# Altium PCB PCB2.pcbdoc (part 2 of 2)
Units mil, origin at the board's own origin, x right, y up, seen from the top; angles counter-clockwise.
Board outline 6543.11 x 5085 mil, 2 copper layers (Top Layer, Bottom Layer); 225 components, 109 nets, 561 pads, 168 vias.
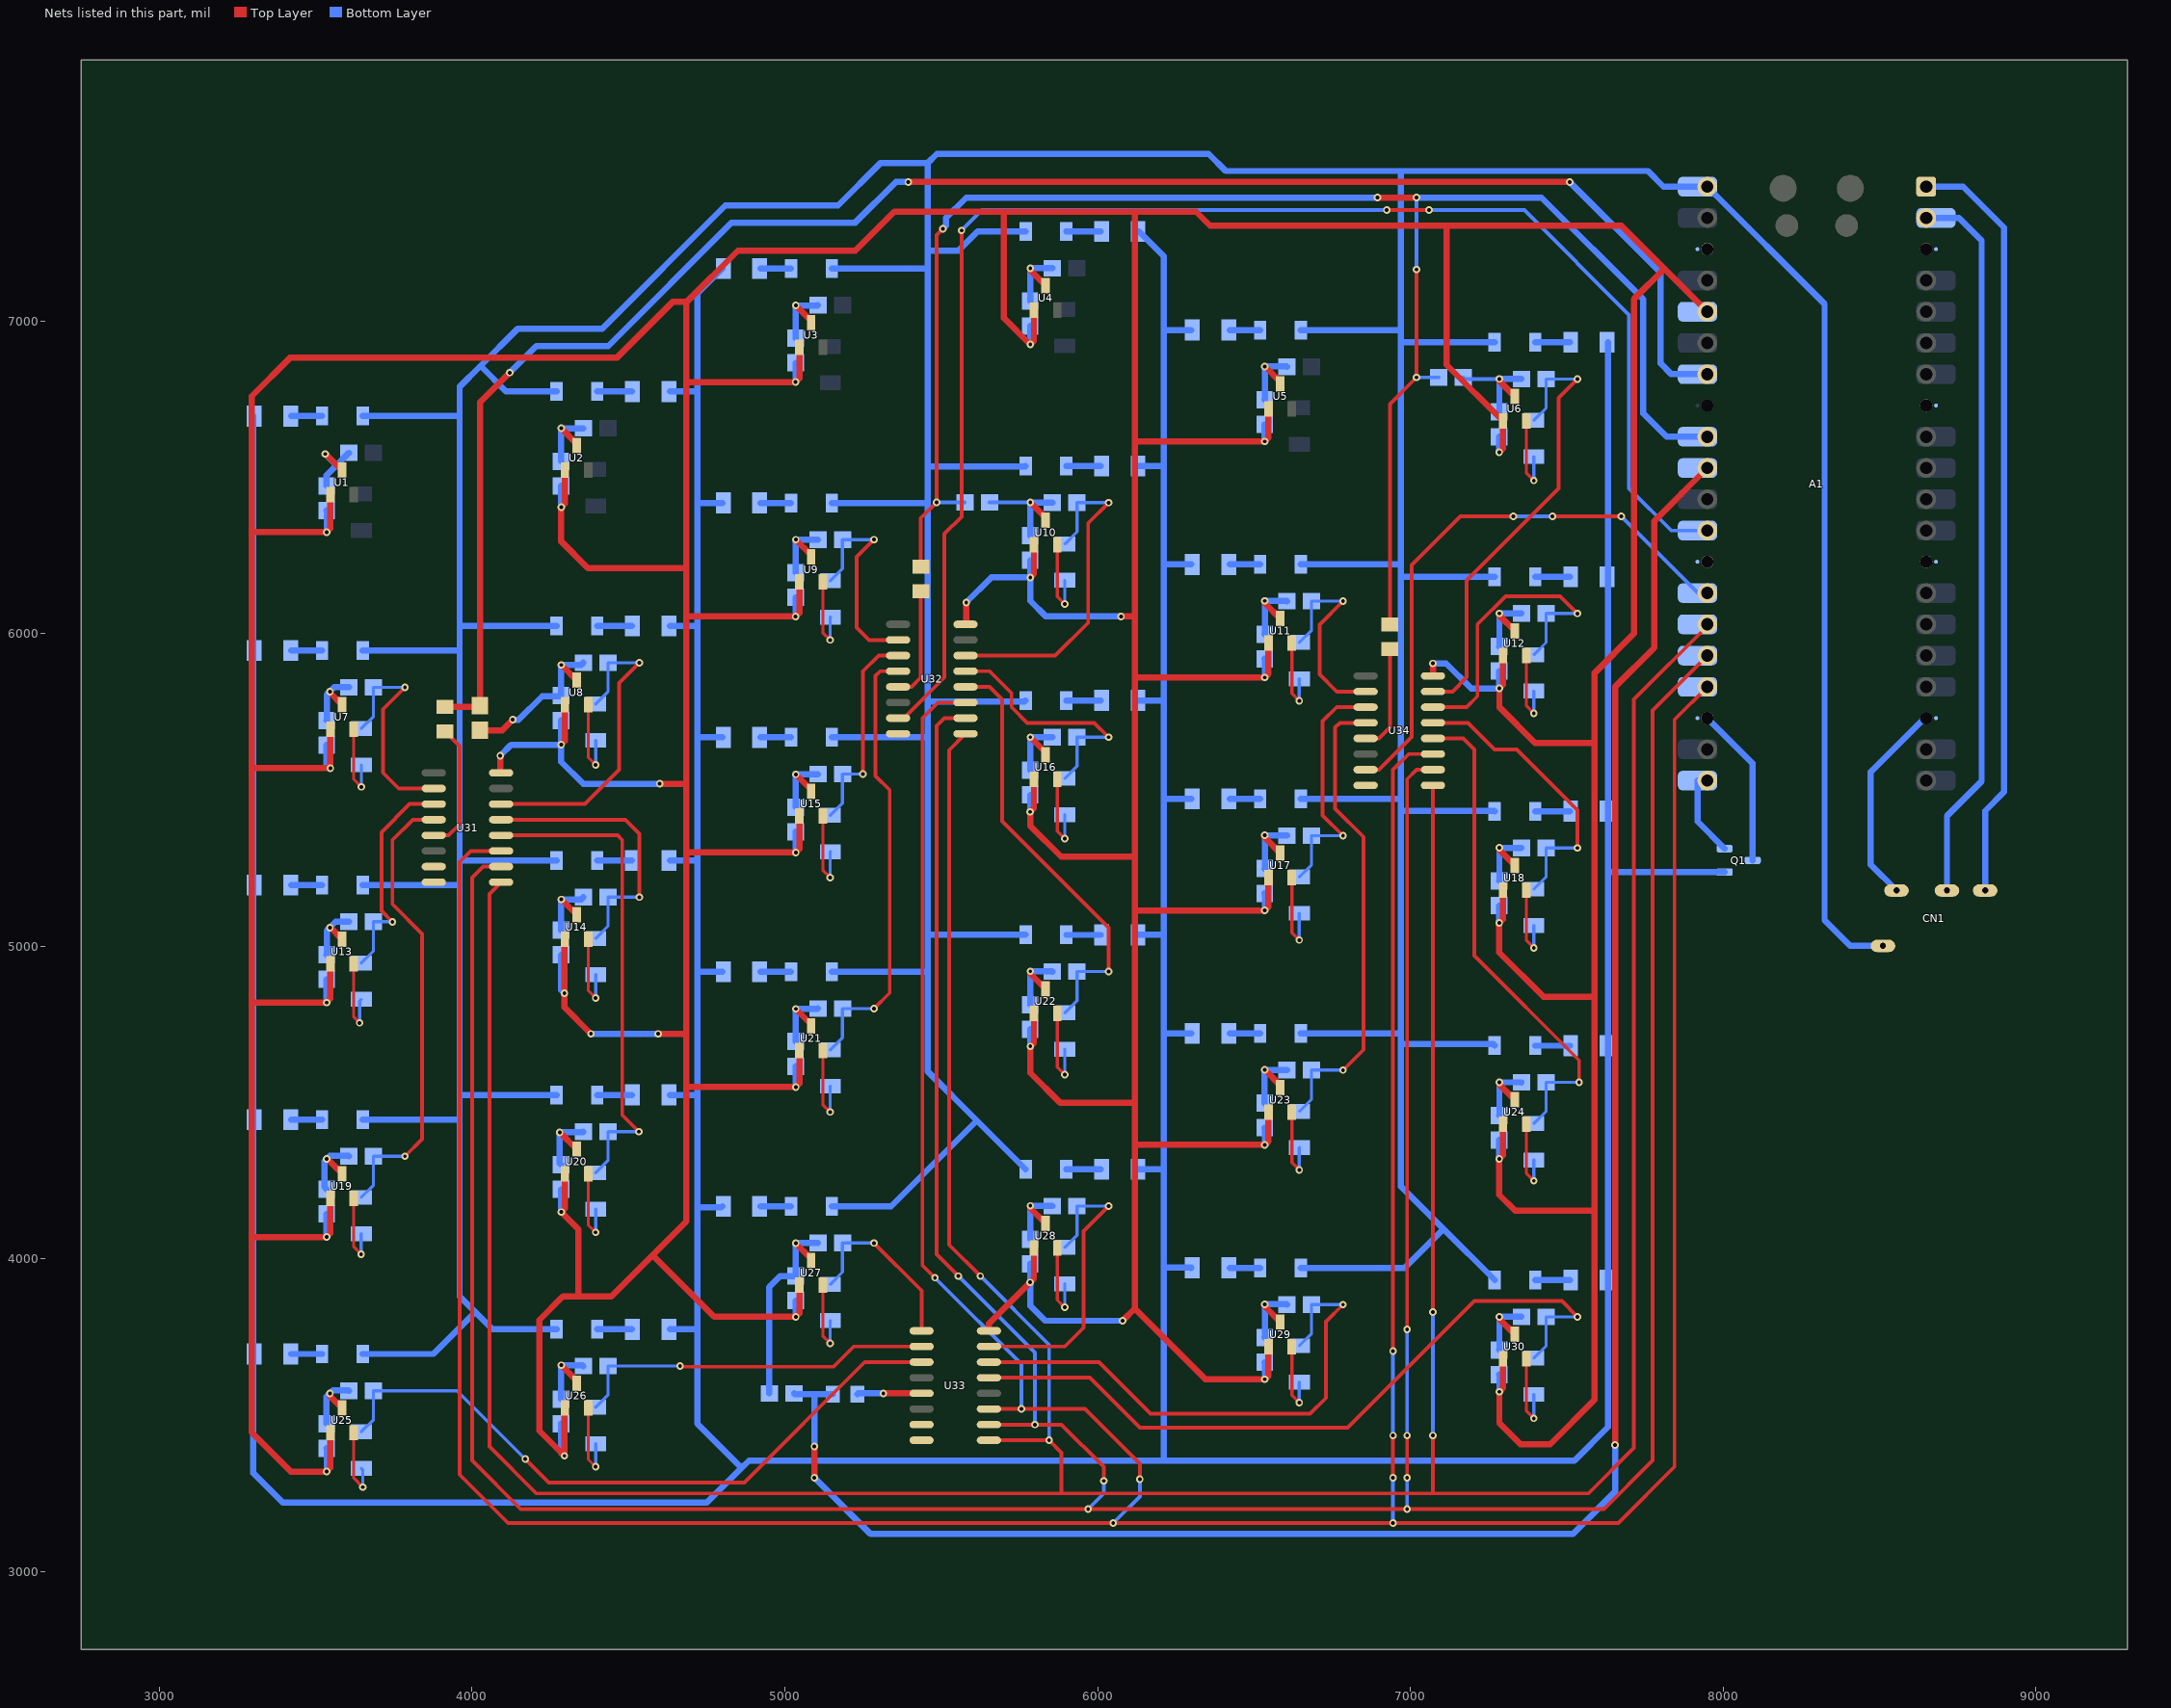
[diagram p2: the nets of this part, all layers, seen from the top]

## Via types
v1: diameter 24.02, hole 12.01, Top Layer to Bottom Layer, 168 vias

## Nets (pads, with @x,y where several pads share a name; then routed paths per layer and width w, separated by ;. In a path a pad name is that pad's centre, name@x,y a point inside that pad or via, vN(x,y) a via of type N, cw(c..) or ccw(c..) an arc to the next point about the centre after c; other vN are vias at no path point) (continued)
$1N19276: R36.2 U6.2 | length 276.8
  Top Layer w10: U6.2@7371.42,6680.31 7371.42,6513.58 v1(7395,6490)
  Bottom Layer w10: v1(7395,6490) 7395,6565.91 R36.2@7395.55,6566.47
$1N19282: C12.2 R36.1 U34.15 | length 1476.1
  Top Layer w12: U34.15@7072.7,5815 7135,5815 7180.45,5860.45 7180.45,6170.45 7475,6465 7475,6754.69 v1(7535,6814.69)
  Bottom Layer w10: R36.1@7395.55,6682.9 7434.41,6721.76 C12.2@7434.41,6814.69 v1(7535,6814.69)
$1N20121: C22.2 R41.1 U34.2 | length 683.7
  Top Layer w12: v1(6785,6104.06) 6710,6029.06 6710,5870 6765,5815 U34.2@6857.3,5815
  Bottom Layer w10: R41.1@6645.55,5972.28 6684.41,6011.13 C22.2@6684.41,6104.06 v1(6785,6104.06)
$1N20126: R41.2 U11.2 | length 265.5
  Top Layer w10: U11.2@6621.42,5969.69 6621.42,5808.58 v1(6645,5785)
  Bottom Layer w10: v1(6645,5785) 6645,5855.28 R41.2@6645.55,5855.84
$1N20136: R42.2 U12.2 | length 266.8
  Top Layer w10: U12.2@7371.42,5930.31 7371.42,5768.58 v1(7395,5745)
  Bottom Layer w10: v1(7395,5745) 7395,5815.91 R42.2@7395.55,5816.47
$1N20142: C20.2 R40.1 U32.14 | length 1095.2
  Top Layer w12: U32.14@5577.7,5930 5865,5930 5970,6035 5970,6354.02 v1(6035,6419.02)
  Bottom Layer w10: R40.1@5895.55,6287.24 5934.41,6326.09 C20.2@5934.41,6419.02 v1(6035,6419.02)
$1N20147: R40.2 U10.2 | length 275.4
  Top Layer w10: U10.2@5871.42,6284.65 5871.42,6118.58 v1(5895,6095)
  Bottom Layer w10: v1(5895,6095) 5895,6170.24 R40.2@5895.55,6170.8
$1N20149: R38.2 U8.2 | length 281.8
  Top Layer w10: U8.2@4371.42,5772.83 4371.42,5603.58 v1(4395,5580)
  Bottom Layer w10: v1(4395,5580) 4395,5658.43 R38.2@4395.55,5658.98
$1N20151: R39.2 U9.2 | length 269.2
  Top Layer w10: U9.2@5121.42,6166.54 5121.42,6003.58 v1(5145,5980)
  Bottom Layer w10: v1(5145,5980) 5145,6052.13 R39.2@5145.55,6052.69
$1N20153: C18.2 R39.1 U32.2 | length 701
  Top Layer w12: v1(5285,6300.91) 5230,6245.91 5230,6020 5270,5980 U32.2@5362.3,5980
  Bottom Layer w10: R39.1@5145.55,6169.13 5184.41,6207.98 C18.2@5184.41,6300.91 v1(5285,6300.91)
$1N20174: C14.2 R37.1 U31.2 | length 733.9
  Top Layer w12: v1(3785,5828.46) 3715,5758.46 3715,5555 3765,5505 U31.2@3877.3,5505
  Bottom Layer w10: R37.1@3645.55,5696.68 3684.41,5735.54 C14.2@3684.41,5828.46 v1(3785,5828.46)
$1N20179: R37.2 U7.2 | length 264.3
  Top Layer w10: U7.2@3621.42,5694.09 3621.42,5534.14 v1(3645.55,5510)
  Bottom Layer w10: v1(3645.55,5510) R37.2@3645.55,5580.24
$1N20185: C16.2 R38.1 U31.14 | length 1040.5
  Top Layer w12: U31.14@4092.7,5455 4360,5455 4470,5565 4470,5842.2 v1(4535,5907.2)
  Bottom Layer w10: R38.1@4395.55,5775.42 4434.41,5814.28 C16.2@4434.41,5907.2 v1(4535,5907.2)
$1N20206: C24.2 R42.1 U34.14 | length 1015.5
  Top Layer w12: U34.14@7072.7,5765 7180,5765 7215,5800 7215,6030 7305,6120 7479.69,6120 v1(7535,6064.69)
  Bottom Layer w10: R42.1@7395.55,5932.9 7434.41,5971.76 C24.2@7434.41,6064.69 v1(7535,6064.69)
$1N21045: C34.2 R47.1 U34.3 | length 797.3
  Top Layer w12: v1(6785,5354.06) 6720,5419.06 6720,5720 6765,5765 U34.3@6857.3,5765
  Bottom Layer w10: R47.1@6645.55,5222.28 6684.41,5261.13 C34.2@6684.41,5354.06 v1(6785,5354.06)
$1N21050: R47.2 U17.2 | length 295.5
  Top Layer w10: U17.2@6621.42,5219.69 6621.42,5043.58 v1(6645,5020)
  Bottom Layer w10: v1(6645,5020) 6645,5105.28 R47.2@6645.55,5105.84
$1N21060: R48.2 U18.2 | length 266.8
  Top Layer w10: U18.2@7371.42,5180.31 7371.42,5018.58 v1(7395,4995)
  Bottom Layer w10: v1(7395,4995) 7395,5065.91 R48.2@7395.55,5066.47
$1N21066: C32.2 R46.1 U32.13 | length 819.5
  Top Layer w12: U32.13@5577.7,5880 5655,5880 5725,5810 5725,5765 5775,5715 5989.02,5715 v1(6035,5669.02)
  Bottom Layer w10: R46.1@5895.55,5537.24 5934.41,5576.09 C32.2@5934.41,5669.02 v1(6035,5669.02)
$1N21071: R46.2 U16.2 | length 275.4
  Top Layer w10: U16.2@5871.42,5534.65 5871.42,5368.58 v1(5895,5345)
  Bottom Layer w10: v1(5895,5345) 5895,5420.24 R46.2@5895.55,5420.8
$1N21073: R44.2 U14.2 | length 271.8
  Top Layer w10: U14.2@4371.42,5022.83 4371.42,4858.58 v1(4395,4835)
  Bottom Layer w10: v1(4395,4835) 4395,4908.43 R44.2@4395.55,4908.98
$1N21075: R45.2 U15.2 | length 289.2
  Top Layer w10: U15.2@5121.42,5416.54 5121.42,5243.58 v1(5145,5220)
  Bottom Layer w10: v1(5145,5220) 5145,5302.13 R45.2@5145.55,5302.69
$1N21077: C30.2 R45.1 U32.3 | length 675.6
  Top Layer w12: v1(5250,5550.91) 5250,5880 5300,5930 U32.3@5362.3,5930
  Bottom Layer w10: R45.1@5145.55,5419.13 5184.41,5457.98 C30.2@5184.41,5550.91 v1(5250,5550.91)
$1N21098: C26.2 R43.1 U31.3 | length 714.1
  Top Layer w12: v1(3745,5078.46) 3710,5113.46 3710,5365 3800,5455 U31.3@3877.3,5455
  Bottom Layer w10: R43.1@3645.55,4946.68 3684.41,4985.54 C26.2@3684.41,5078.46 v1(3745,5078.46)
$1N21103: R43.2 U13.2 | length 274.3
  Top Layer w10: U13.2@3621.42,4944.09 3621.42,4773.58 v1(3640,4755)
  Bottom Layer w10: v1(3640,4755) 3640,4824.69 R43.2@3645.55,4830.24
$1N21109: C28.2 R44.1 U31.13 | length 912.2
  Top Layer w12: U31.13@4092.7,5405 4490,5405 4535,5360 v1(4535,5157.2)
  Bottom Layer w10: R44.1@4395.55,5025.42 4434.41,5064.28 C28.2@4434.41,5157.2 v1(4535,5157.2)
$1N21130: C36.2 R48.1 U34.13 | length 947.1
  Top Layer w12: U34.13@7072.7,5715 7185,5715 7270,5630 7340,5630 7535,5435 v1(7535,5314.69)
  Bottom Layer w10: R48.1@7395.55,5182.9 7434.41,5221.76 C36.2@7434.41,5314.69 v1(7535,5314.69)
$1N21969: C46.2 R53.1 U34.4 | length 1512.1
  Top Layer w12: v1(6785,4604.06) 6850,4669.06 6850,5350 6760,5440 6760,5700 6775,5715 U34.4@6857.3,5715
  Bottom Layer w10: R53.1@6645.55,4472.28 6684.41,4511.13 C46.2@6684.41,4604.06 v1(6785,4604.06)
$1N21974: R53.2 U23.2 | length 265.5
  Top Layer w10: U23.2@6621.42,4469.69 6621.42,4308.58 v1(6645,4285)
  Bottom Layer w10: v1(6645,4285) 6645,4355.28 R53.2@6645.55,4355.84
$1N21984: R54.2 U24.2 | length 256.8
  Top Layer w10: U24.2@7371.42,4430.31 7371.42,4273.58 v1(7395,4250)
  Bottom Layer w10: v1(7395,4250) 7395,4315.91 R54.2@7395.55,4316.47
$1N21990: C44.2 R52.1 U32.12 | length 1394.2
  Top Layer w12: U32.12@5577.7,5830 5655,5830 5695,5790 5695,5400 6035,5060 v1(6035,4919.02)
  Bottom Layer w10: R52.1@5895.55,4787.24 5934.41,4826.09 C44.2@5934.41,4919.02 v1(6035,4919.02)
$1N21995: R52.2 U22.2 | length 285.4
  Top Layer w10: U22.2@5871.42,4784.65 5871.42,4613.58 v1(5895,4590)
  Bottom Layer w10: v1(5895,4590) 5895,4670.24 R52.2@5895.55,4670.8
$1N21997: R50.2 U20.2 | length 271.8
  Top Layer w10: U20.2@4371.42,4272.83 4371.42,4108.58 v1(4395,4085)
  Bottom Layer w10: v1(4395,4085) 4395,4158.43 R50.2@4395.55,4158.98
$1N21999: R51.2 U21.2 | length 289.2
  Top Layer w10: U21.2@5121.42,4666.54 5121.42,4493.58 v1(5145,4470)
  Bottom Layer w10: v1(5145,4470) 5145,4552.13 R51.2@5145.55,4552.69
$1N22001: C42.2 R51.1 U32.4 | length 1430.4
  Top Layer w12: v1(5285,4800.91) 5335,4850.91 5335,5500 5290,5545 5290,5865 5305,5880 U32.4@5362.3,5880
  Bottom Layer w10: R51.1@5145.55,4669.13 5184.41,4707.98 C42.2@5184.41,4800.91 v1(5285,4800.91)
$1N22022: C38.2 R49.1 U31.4 | length 1481.4
  Top Layer w12: v1(3785,4328.46) 3840,4383.46 3840,5040 3745,5135 3745,5340 3810,5405 U31.4@3877.3,5405
  Bottom Layer w10: R49.1@3645.55,4196.68 3684.41,4235.54 C38.2@3684.41,4328.46 v1(3785,4328.46)
$1N22027: R49.2 U19.2 | length 254.3
  Top Layer w10: U19.2@3621.42,4194.09 3621.42,4038.58 v1(3645,4015)
  Bottom Layer w10: v1(3645,4015) 3645,4079.69 R49.2@3645.55,4080.24
$1N22033: C40.2 R50.1 U31.12 | length 1594.4
  Top Layer w12: U31.12@4092.7,5355 4465,5355 4480,5340 4480,4460 v1(4532.8,4407.2)
  Bottom Layer w10: R50.1@4395.55,4275.42 4434.41,4314.28 C40.2@4434.41,4407.2 v1(4532.8,4407.2)
$1N22054: C48.2 R54.1 U34.12 | length 1604.3
  Top Layer w12: U34.12@7072.7,5665 7170,5665 7205,5630 7205,4970 7540,4635 v1(7540,4564.69)
  Bottom Layer w10: R54.1@7395.55,4432.9 7434.41,4471.76 C48.2@7434.41,4564.69 v1(7540,4564.69)
$1N22893: C58.2 R59.1 U33.14 | length 1736.7
  Top Layer w12: U33.14@5652.7,3670 6005,3670 6170,3505 6680,3505 6730,3555 6730,3799.06 v1(6785,3854.06)
  Bottom Layer w10: R59.1@6645.55,3722.28 6684.41,3761.13 C58.2@6684.41,3854.06 v1(6785,3854.06)
$1N22898: R59.2 U29.2 | length 255.5
  Top Layer w10: U29.2@6621.42,3719.69 6621.42,3563.58 v1(6645,3540)
  Bottom Layer w10: v1(6645,3540) 6645,3605.28 R59.2@6645.55,3605.84
$1N22908: R60.2 U30.2 | length 276.8
  Top Layer w10: U30.2@7371.42,3680.32 7371.42,3513.58 v1(7395,3490)
  Bottom Layer w10: v1(7395,3490) 7395,3565.91 R60.2@7395.55,3566.47
$1N22914: C56.2 R58.1 U33.15 | length 997.8
  Top Layer w12: U33.15@5652.7,3720 5895,3720 5955,3780 5955,4089.02 v1(6035,4169.02)
  Bottom Layer w10: R58.1@5895.55,4037.24 5934.41,4076.09 C56.2@5934.41,4169.02 v1(6035,4169.02)
$1N22919: R58.2 U28.2 | length 275.4
  Top Layer w10: U28.2@5871.42,4034.65 5871.42,3868.58 v1(5895,3845)
  Bottom Layer w10: v1(5895,3845) 5895.55,3845.55 R58.2@5895.55,3920.8
$1N22921: R56.2 U26.2 | length 271.8
  Top Layer w10: U26.2@4371.42,3522.83 4371.42,3358.58 v1(4395,3335)
  Bottom Layer w10: v1(4395,3335) 4395,3408.43 R56.2@4395.55,3408.98
$1N22923: R57.2 U27.2 | length 269.2
  Top Layer w10: U27.2@5121.42,3916.54 5121.42,3753.58 v1(5145,3730)
  Bottom Layer w10: v1(5145,3730) 5145,3802.13 R57.2@5145.55,3802.69
$1N22925: C54.2 R57.1 U33.1 | length 592.5
  Top Layer w12: v1(5285,4050.91) 5437.3,3898.61 U33.1@5437.3,3770
  Bottom Layer w10: R57.1@5145.55,3919.13 5184.41,3957.98 C54.2@5184.41,4050.91 v1(5285,4050.91)
$1N22946: C50.2 R55.1 U33.3 | length 2181.9
  Top Layer w12: v1(4170,3360) 4170,3359.82 4244.82,3285 4870,3285 5255,3670 U33.3@5437.3,3670
  Bottom Layer w10: R55.1@3645.55,3446.68 3684.41,3485.54 C50.2@3684.41,3578.46 3951.54,3578.46 v1(4170,3360)
$1N22951: R55.2 U25.2 | length 248
  Top Layer w10: U25.2@3621.42,3444.09 3621.42,3298.58 v1(3650,3270)
  Bottom Layer w10: R55.2@3645.55,3330.24 3650,3325.8 v1(3650,3270)
$1N22957: C52.2 R56.1 U33.2 | length 1178.6
  Top Layer w12: v1(4665,3657.2) 4667.2,3655 5155,3655 5220,3720 U33.2@5437.3,3720
  Bottom Layer w10: R56.1@4395.55,3525.42 4434.41,3564.28 C52.2@4434.41,3657.2 v1(4665,3657.2)
$1N22978: C60.2 R60.1 U33.13 | length 2385.6
  Top Layer w12: U33.13@5652.7,3620 5975,3620 6135,3460 6800,3460 7205,3865 7484.69,3865 v1(7535,3814.68)
  Bottom Layer w10: R60.1@7395.55,3682.91 7434.41,3721.76 C60.2@7434.41,3814.68 v1(7535,3814.68)
$1N29883: R63.2 U34.5 | length 342.8
  Top Layer w12: U34.5@6857.3,5665 6900,5665 6935,5700 R63.2@6935,5950.63
$1N29959: R64.2 U33.5 | length 206.8
  Top Layer w20: v1(5315,3570) U33.5@5437.3,3570
  Bottom Layer w20: R64.2@5231.66,3567.21 5234.45,3570 v1(5315,3570)
$1N30613: R61.2 U31.5 | length 414.6
  Top Layer w12: U31.5@3877.3,5355 3925,5355 3960,5390 3960,5640.63 R61.2@3912.77,5687.86
$1N30615: R62.2 U32.5 | length 360.8
  Top Layer w12: U32.5@5362.3,5830 5405,5830 5435,5860 R62.2@5435,6135.63
$2N2161: Q1.1 R1.1 R2.1 R3.1 R4.1 R5.1 R6.1 R7.1 R8.1 R9.1 R10.1 R11.1 R12.1 R13.1 R14.1 R15.1 R16.1 R17.1 R18.1 R19.1 R20.1 R21.1 R22.1 R23.1 R24.1 R25.1 R26.1 R27.1 R28.1 R29.1 R30.1 | length 21120.1
  Bottom Layer w19.68: R30.1@7632.24,3932.2 7632.24,5237.19 R6.1@7632.24,6932.2
  Bottom Layer w20: R1.1@3300.2,6695.98 3300.2,3314.8 3395,3220 4750,3220 4861.37,3331.37 ; R26.1@4632.24,3774.72 4718.49,3774.72 4720,3773.21 ; R20.1@4632.24,4524.72 4717.79,4524.72 4720,4526.93 ; R14.1@4632.24,5274.72 4719.97,5274.72 ; R8.1@4632.24,6024.72 4719.78,6024.72 4720,6024.94 ; R2.1@4632.24,6774.72 4719.22,6774.72 4720,6773.94 ; R27.1@4800.2,4168.43 4796.59,4164.82 4720,4164.82 ; R21.1@4800.2,4918.43 4722.47,4918.43 4720,4920.9 ; R15.1@4800.2,5668.43 4720.3,5668.43 4720,5668.72 ; R9.1@4800.2,6418.43 4720.48,6418.43 4720,6418.9 ; R3.1@4800.2,7168.43 4720,7088.23 4720,6773.94 ; R28.1@6132.24,4286.54 6210.55,4286.54 6212.42,4288.41 ; R22.1@6132.24,5036.54 6211.42,5036.54 6212.42,5037.54 ; R16.1@6132.24,5786.54 6212.28,5786.54 6212.42,5786.67 ; R10.1@6132.24,6536.54 6211.84,6536.54 6212.42,6537.12 ; R4.1@6132.24,7286.54 6212.42,7206.36 6212.42,6968.83 ; R29.1@6300.2,3971.57 6299.23,3972.54 6212.42,3972.54 ; R23.1@6300.2,4721.57 6216.99,4721.57 6212.42,4726.14 ; R17.1@6300.2,5471.57 6213.5,5471.57 6212.42,5472.66 ; R11.1@6300.2,6221.57 6213.16,6221.57 6212.42,6222.31 ; R5.1@6300.2,6971.57 6215.17,6971.57 6212.42,6968.83 ; R30.1@7632.24,3932.2 7632.24,3462.24 7525,3355 6214.77,3355 ; 7632.24,5237.19 7632.65,5237.6 Q1.1@8005.22,5237.6 ; 4720,3773.21 4720,3472.74 4861.37,3331.37 ; 4720,3773.21 4720,4164.82 ; 4720,4164.82 4720,4526.93 ; 4720,4526.93 4720,4920.9 ; 4720,4920.9 4720,5274.76 4720,5668.72 ; 4720,5668.72 4720,6024.94 ; 4720,6024.94 4720,6418.9 ; 4720,6418.9 4720,6773.94 ; 4861.37,3331.37 4885,3355 6214.77,3355 ; 6212.42,3972.54 6212.42,4288.41 ; 6212.42,3972.54 6212.42,3357.35 6214.77,3355 ; 6212.42,4288.41 6212.42,4726.14 ; 6212.42,4726.14 6212.42,5037.54 ; 6212.42,5037.54 6212.42,5472.66 ; 6212.42,5472.66 6212.42,5786.67 ; 6212.42,5786.67 6212.42,6222.31 ; 6212.42,6222.31 6212.42,6537.12 ; 6212.42,6537.12 6212.42,6968.83
$2N2235: D4.1 R4.2 | length 110.2
  Bottom Layer w19.68: D4.1@5900,7286.54 R4.2@6010.2,7286.54
$2N2237: D1.1 R1.2 | length 97.8
  Bottom Layer w20: R1.2@3422.24,6695.98 D1.1@3520,6695.98
$2N2239: D17.1 R17.2 | length 97.8
  Bottom Layer w20: R17.2@6422.24,5471.57 D17.1@6520,5471.57
$2N2241: D24.1 R24.2 | length 110.2
  Bottom Layer w19.68: D24.1@7400,4682.2 R24.2@7510.2,4682.2
$2N2243: D9.1 R9.2 | length 97.8
  Bottom Layer w20: R9.2@4922.24,6418.43 D9.1@5020,6418.43
$2N2245: D7.1 R7.2 | length 97.8
  Bottom Layer w20: R7.2@3422.24,5945.98 D7.1@3520,5945.98
$2N2247: D21.1 R21.2 | length 97.8
  Bottom Layer w20: R21.2@4922.24,4918.43 D21.1@5020,4918.43
$2N2249: D8.1 R8.2 | length 110.2
  Bottom Layer w20: D8.1@4400,6024.72 R8.2@4510.2,6024.72
$2N2251: D15.1 R15.2 | length 97.8
  Bottom Layer w20: R15.2@4922.24,5668.43 D15.1@5020,5668.43
$2N2253: D12.1 R12.2 | length 110.2
  Bottom Layer w19.68: D12.1@7400,6182.2 R12.2@7510.2,6182.2
$2N2255: D18.1 R18.2 | length 110.2
  Bottom Layer w19.68: D18.1@7400,5432.2 R18.2@7510.2,5432.2
$2N2257: D19.1 R19.2 | length 97.8
  Bottom Layer w20: R19.2@3422.24,4445.98 D19.1@3520,4445.98
$2N2259: D3.1 R3.2 | length 97.8
  Bottom Layer w20: R3.2@4922.24,7168.43 D3.1@5020,7168.43
$2N2261: D13.1 R13.2 | length 97.8
  Bottom Layer w20: R13.2@3422.24,5195.98 D13.1@3520,5195.98
$2N2263: D25.1 R25.2 | length 97.8
  Bottom Layer w20: R25.2@3422.24,3695.98 D25.1@3520,3695.98
$2N2265: D22.1 R22.2 | length 110.2
  Bottom Layer w19.68: D22.1@5900,5036.54 R22.2@6010.2,5036.54
$2N2267: D5.1 R5.2 | length 97.8
  Bottom Layer w20: R5.2@6422.24,6971.57 D5.1@6520,6971.57
$2N2269: D11.1 R11.2 | length 97.8
  Bottom Layer w20: R11.2@6422.24,6221.57 D11.1@6520,6221.57
$2N2271: D6.1 R6.2 | length 110.2
  Bottom Layer w19.68: D6.1@7400,6932.2 R6.2@7510.2,6932.2
$2N2273: D10.1 R10.2 | length 110.2
  Bottom Layer w19.68: D10.1@5900,6536.54 R10.2@6010.2,6536.54
$2N2275: D26.1 R26.2 | length 110.2
  Bottom Layer w20: D26.1@4400,3774.72 R26.2@4510.2,3774.72
$2N2277: D28.1 R28.2 | length 110.2
  Bottom Layer w19.68: D28.1@5900,4286.54 R28.2@6010.2,4286.54
$2N2279: D29.1 R29.2 | length 97.8
  Bottom Layer w20: R29.2@6422.24,3971.57 D29.1@6520,3971.57
$2N2281: D14.1 R14.2 | length 110.2
  Bottom Layer w20: D14.1@4400,5274.72 R14.2@4510.2,5274.72
$2N2283: D16.1 R16.2 | length 110.2
  Bottom Layer w19.68: D16.1@5900,5786.54 R16.2@6010.2,5786.54
$2N2285: D27.1 R27.2 | length 97.8
  Bottom Layer w20: R27.2@4922.24,4168.43 D27.1@5020,4168.43
$2N2287: D30.1 R30.2 | length 110.2
  Bottom Layer w20: D30.1@7400,3932.2 R30.2@7510.2,3932.2
$2N2289: D23.1 R23.2 | length 97.8
  Bottom Layer w20: R23.2@6422.24,4721.57 D23.1@6520,4721.57
$2N2291: D20.1 R20.2 | length 110.2
  Bottom Layer w20: D20.1@4400,4524.72 R20.2@4510.2,4524.72
$2N2293: D2.1 R2.2 | length 110.2
  Bottom Layer w20: D2.1@4400,6774.72 R2.2@4510.2,6774.72
ADC_0: A1.31 C64.1 R64.1 | length 6480
  Top Layer w20: v1(5094.59,3300) v1(5094.59,3400) ; v1(7655,3405) 7655,5830 7780,5955 7780,6360 A1.31@7950,6530
  Bottom Layer w20: C64.1@5029.37,3570 5032.16,3567.21 5094.59,3567.21 ; v1(5094.59,3300) 5274.59,3120 7520,3120 7655,3255 v1(7655,3405) ; v1(5094.59,3400) 5094.59,3567.21 ; R64.1@5152.92,3567.21 5094.59,3567.21
ADC_1: A1.32 C62.1 C63.1 R62.1 R63.1 | length 5672
  Top Layer w12: R62.1@5435,6214.37 5435,6370 v1(5485,6420) 5485,7275 v1(5505,7295) ; R63.1@6935,6029.37 6935,6735 v1(7020,6820) v1(7020,7165)
  Top Layer w20: v1(6895,7395) v1(7020,7395)
  Bottom Layer w12: v1(5485,6420) C62.1@5575.63,6420 ; v1(7020,6820) C63.1@7090.63,6820 ; v1(7020,7165) v1(7020,7395)
  Bottom Layer w20: v1(5505,7295) 5515,7305 5515,7330 5580,7395 v1(6895,7395) ; v1(7020,7395) 7420,7395 7745,7070 7745,6705 7820,6630 A1.32@7918.5,6630
ADC_2: A1.34 C61.1 R61.1 | length 5701.2
  Top Layer w20: R61.1@3912.77,5766.6 4022.23,5766.6 C61.1@4025,5769.37 4025,6740 v1(4120,6835) ; v1(5395,7445) v1(7510,7445) ; A1.34@7945,6835 A1.34@7950,6830
  Bottom Layer w20: v1(4120,6835) 4205,6920 4435,6920 4830,7315 5225,7315 5355,7445 v1(5395,7445) ; v1(7510,7445) 7800,7155 7800,6865 7835,6830 A1.34@7918.5,6830
GND: A1.3 A1.8 A1.13 A1.18 A1.23 A1.28 A1.38 C1.2 C2.1 C3.2 C4.1 C5.2 C6.1 C7.2 C8.1 C9.2 C10.1 C11.2 C12.1 C13.2 C14.1 C15.2 C16.1 C17.2 C18.1 C19.2 C20.1 C21.2 C22.1 C23.2 C24.1 C25.2 C26.1 C27.2 C28.1 C29.2 C30.1 C31.2 C32.1 C33.2 C34.1 C35.2 C36.1 C37.2 C38.1 C39.2 C40.1 C41.2 C42.1 C43.2 C44.1 C45.2 C46.1 C47.2 C48.1 C49.2 C50.1 C51.2 C52.1 C53.2 C54.1 C55.2 C56.1 C57.2 C58.1 C59.2 C60.1 C61.2 C62.2 C63.2 C64.2 CN1.4 Q1.3 U1.3 U2.3 U3.3 U4.3 U5.3 U6.3 U7.3 U8.3 U9.3 U10.3 U11.3 U12.3 U13.3 U14.3 U15.3 U16.3 U17.3 U18.3 U19.3 U20.3 U21.3 U22.3 U23.3 U24.3 U25.3 U26.3 U27.3 U28.3 U29.3 U30.3 U31.7 U31.8 U32.8 U33.7 U33.8 U34.8 | length 9662
  Top Layer w20: v1(3530,6575) 3531.85,6575 U1.3@3584.02,6522.83 ; v1(3535,4320) 3536.85,4320 U19.3@3584.02,4272.83 ; v1(3545,3570) 3545,3561.85 U25.3@3584.02,3522.83 ; v1(3545,5060) 3546.85,5060 U13.3@3584.02,5022.83 ; v1(3545,5815) 3545,5811.85 U7.3@3584.02,5772.83 ; C61.2@4025,5690.63 4095.63,5690.63 v1(4130,5725) ; v1(4280,4405) 4280.59,4405 U20.3@4334.02,4351.57 ; v1(4285,3660) 4334.02,3610.98 U26.3@4334.02,3601.57 ; v1(4285,5150) 4285.59,5150 U14.3@4334.02,5101.57 ; v1(4285,5900) 4285.59,5900 U8.3@4334.02,5851.57 ; v1(4285,6657.2) 4334.02,6608.19 U2.3@4334.02,6601.57 ; v1(5035,4050) 5084.02,4000.98 U27.3@5084.02,3995.28 ; v1(5035,4800) 5084.02,4750.98 U21.3@5084.02,4745.28 ; v1(5035,5550) 5084.02,5500.98 U15.3@5084.02,5495.28 ; v1(5035,6300.91) 5084.02,6251.89 U9.3@5084.02,6245.28 ; v1(5035,7050) 5084.02,7000.98 U3.3@5084.02,6995.28 ; v1(5785,4170) 5785,4162.4 U28.3@5834.02,4113.39 ; v1(5785,4920) 5785,4912.4 U22.3@5834.02,4863.39 ; v1(5785,5669.02) 5834.02,5620 U16.3@5834.02,5613.39 ; v1(5785,6420) 5834.02,6370.98 U10.3@5834.02,6363.39 ; v1(5785,7169.02) 5785,7162.4 U4.3@5834.02,7113.39 ; v1(6535,3855) 6535,3847.44 U29.3@6584.02,3798.43 ; v1(6535,4605) 6584.02,4555.98 U23.3@6584.02,4548.43 ; v1(6535,5355) 6535,5347.44 U17.3@6584.02,5298.43 ; v1(6535,6105) 6535,6097.44 U11.3@6584.02,6048.43 ; v1(6535,6855) 6584.02,6805.98 U5.3@6584.02,6798.43 ; v1(7285,3815) 7285,3808.07 U30.3@7334.02,3759.05 ; v1(7285,4565) 7285,4558.07 U24.3@7334.02,4509.06 ; v1(7285,5315) 7285,5308.07 U18.3@7334.02,5259.06 ; v1(7285,6065) 7285,6058.07 U12.3@7334.02,6009.06 ; v1(7285,6815) 7285,6808.07 U6.3@7334.02,6759.06
  Bottom Layer w12: C62.2@5654.37,6420 v1(5785,6420) ; C63.2@7169.37,6820 7174.37,6815 v1(7285,6815)
  Bottom Layer w19.68: A1.23@7950,5730 8094.78,5585.22 Q1.3@8094.78,5275 ; CN1.4@8554.92,5178.58 8472.73,5260.77 8472.73,5557.73 8645,5730 A1.18@8650,5730
  Bottom Layer w20: v1(3530,6575) 3565.43,6539.57 3566.77,6539.57 ; C49.2@3534.53,3472.83 3534.53,3559.53 v1(3545,3570) 3555,3580 3604.13,3580 C50.1@3605.67,3578.46 ; C37.2@3534.53,4222.83 3527.5,4229.86 3527.5,4312.5 v1(3535,4320) 3545,4330 3604.13,4330 C38.1@3605.67,4328.46 ; C25.2@3534.53,4972.83 3535,4973.31 3535,5050 v1(3545,5060) 3563.46,5078.46 C26.1@3605.67,5078.46 ; C13.2@3534.53,5722.83 3535,5723.31 3535,5805 v1(3545,5815) 3558.46,5828.46 C14.1@3605.67,5828.46 ; C1.2@3534.53,6472.83 3534.53,6507.32 3566.77,6539.57 ; C2.1@3605.67,6578.46 3566.77,6539.57 ; v1(4130,5725) 4149.14,5725 4224.14,5800 4282.95,5800 C15.2@4284.53,5801.57 4285,5802.05 v1(4285,5900) 4348.46,5900 C16.1@4355.67,5907.2 ; C51.2@4284.53,3551.57 4285,3552.05 v1(4285,3660) 4352.87,3660 C52.1@4355.67,3657.2 ; C39.2@4284.53,4301.57 4280,4306.1 v1(4280,4405) 4353.46,4405 C40.1@4355.67,4407.2 ; C27.2@4284.53,5051.57 4285,5052.05 v1(4285,5150) 4348.46,5150 C28.1@4355.67,5157.2 ; C3.2@4284.53,6551.57 4285,6552.05 v1(4285,6657.2) C4.1@4355.67,6657.2 ; C64.2@4950.63,3570 4950,3570.63 4950,3910 4985.28,3945.28 C53.2@5034.53,3945.28 5034.53,4049.53 v1(5035,4050) 5035.91,4050.91 C54.1@5105.67,4050.91 ; C41.2@5034.53,4695.28 5035,4695.75 v1(5035,4800) 5104.76,4800 C42.1@5105.67,4800.91 ; C29.2@5034.53,5445.28 5034.53,5549.53 v1(5035,5550) 5035.91,5550.91 C30.1@5105.67,5550.91 ; C17.2@5034.53,6195.28 5035,6195.75 v1(5035,6300.91) C18.1@5105.67,6300.91 ; C5.2@5034.53,6945.28 5035,6945.75 v1(5035,7050) 5104.76,7050 C6.1@5105.67,7050.91 ; C55.2@5784.53,4063.39 5785,4063.86 v1(5785,4170) 5854.69,4170 C56.1@5855.67,4169.02 ; C43.2@5784.53,4813.39 5785,4813.86 v1(5785,4920) 5854.69,4920 C44.1@5855.67,4919.02 ; C31.2@5784.53,5563.39 5784.53,5668.54 v1(5785,5669.02) C32.1@5855.67,5669.02 ; C19.2@5784.53,6313.39 5785,6313.86 v1(5785,6420) 5854.69,6420 C20.1@5855.67,6419.02 ; C7.2@5784.53,7063.39 5784.53,7168.54 v1(5785,7169.02) C8.1@5855.67,7169.02 ; C57.2@6534.53,3748.43 6535,3748.9 v1(6535,3855) 6604.72,3855 C58.1@6605.67,3854.06 ; C45.2@6534.53,4498.43 6534.53,4603.58 v1@6535,4604.06 ; C33.2@6534.53,5248.43 6535,5248.9 v1(6535,5355) 6604.72,5355 C34.1@6605.67,5354.06 ; C21.2@6534.53,5998.43 6535,5998.9 v1(6535,6105) 6604.72,6105 C22.1@6605.67,6104.06 ; C9.2@6534.53,6748.43 6535,6748.9 v1(6535,6855) 6604.72,6855 C10.1@6605.67,6854.06 ; v1(6535,4605) v1@6535,4604.06 ; C46.1@6605.67,4604.06 v1@6535,4604.06 ; C59.2@7284.53,3709.05 7285,3709.53 v1(7285,3815) 7355.35,3815 C60.1@7355.67,3814.68 ; C47.2@7284.53,4459.06 7285,4459.53 v1(7285,4565) 7355.35,4565 C48.1@7355.67,4564.69 ; C35.2@7284.53,5209.06 7285,5209.53 v1(7285,5315) 7355.35,5315 C36.1@7355.67,5314.69 ; C23.2@7284.53,5959.06 7285,5959.53 v1(7285,6065) 7355.35,6065 C24.1@7355.67,6064.69 ; C11.2@7284.53,6709.06 7285,6709.53 v1(7285,6815) 7355.35,6815 C12.1@7355.67,6814.69
M3ENABLE: A1.29 U32.7 | length 4815.9
  Top Layer w12: U32.7@5362.3,5730 5380,5730 5510,5860 5510,6319.41 5565,6374.41 v1(5565,7290) ; v1(6925,7355) v1(7060,7355)
  Bottom Layer w10: A1.29@7918.5,6330 A1.29@7950,6330
  Bottom Layer w12: v1(5565,7290) 5630,7355 v1(6925,7355) ; v1(7060,7355) 7365,7355 7700,7020 7700,6465 7835,6330 A1.29@7918.5,6330
M4ENABLE: A1.27 U34.7 | length 1851.9
  Top Layer w12: U34.7@6857.3,5565 6900,5565 7005,5670 7005,6220 7160,6375 v1(7330,6375) ; v1(7455,6375) v1(7675,6375)
  Bottom Layer w12: v1(7330,6375) v1(7455,6375) ; v1(7675,6375) 7920,6130 A1.27@7950,6130
PWM_SIGNAL: A1.21 Q1.2 | length 253.5
  Bottom Layer w19.68: A1.21@7918.5,5530 7918.5,5399.11 Q1.2@8005.22,5312.4
S0: A1.24 U31.11 U32.11 U33.11 U34.11 | length 14507.4
  Top Layer w12: U31.11@4092.7,5305 3995,5305 3960,5270 3960,3310 4115,3155 v1(6050,3155) v1(6945,3155) 7665,3155 7845,3335 7845,5725 A1.24@7950,5830 ; v1(5480,3940) 5440,3980 5440,5730 5490,5780 U32.11@5577.7,5780 ; U33.11@5652.7,3520 v1@5756.72,3520 ; v1(5756.76,3520) 5960,3520 6135,3345 v1(6135,3295) ; v1(6945,3300) v1(6945,3435) ; v1(6945,3705) 6945,5565 6995,5615 U34.11@7072.7,5615
  Bottom Layer w12: v1(5480,3940) 5756.76,3663.24 v1(5756.76,3520) ; v1(6050,3155) 6135,3240 v1(6135,3295) ; v1(6945,3155) v1(6945,3300) ; v1(6945,3435) v1(6945,3705)
S1: A1.25 U31.10 U32.10 U33.10 U34.10 | length 14000.7
  Top Layer w12: U31.10@4092.7,5255 4035,5255 4000,5220 4000,3355 4155,3200 v1(5970,3200) v1(6990,3200) 7620,3200 7775,3355 7775,5755 A1.25@7950,5930 ; v1(5555,3945) 5485,4015 5485,5705 5510,5730 U32.10@5577.7,5730 ; U33.10@5652.7,3470 v1(5800,3470) 5885,3470 6020,3335 v1(6020,3290) ; v1(6990,3300) v1(6990,3435) ; v1(6990,3775) 6990,5535 7020,5565 U34.10@7072.7,5565
  Bottom Layer w12: v1(5555,3945) 5800,3700 v1(5800,3470) ; v1(5970,3200) 6020,3250 v1(6020,3290) ; v1(6990,3200) v1(6990,3300) ; v1(6990,3435) v1(6990,3775)
S2: A1.26 U31.9 U32.9 U33.9 U34.9 | length 13393.3
  Top Layer w12: U31.9@4092.7,5205 4055,5167.3 4055,3400 4205,3250 5884.51,3250 ; U32.9@5577.7,5680 5525,5627.3 5525,4045 v1(5625,3945) ; U33.9@5652.7,3420 v1(5845,3420) 5884.51,3380.49 5884.51,3250 ; v1(7072.7,3435) 7072.7,3250.33 7072.37,3250 ; v1(7072.7,3830) U34.9@7072.7,5515 ; A1.26@7950,6030 7950,6025 7715,5790 7715,3395 7570,3250 7072.37,3250 ; 5884.51,3250 7072.37,3250
  Bottom Layer w12: v1(5625,3945) 5845,3725 v1(5845,3420) ; v1(7072.7,3435) v1(7072.7,3830)
UART_RX: A1.2 CN1.3 | length 2300.7
  Bottom Layer w19.68: A1.2@8681.5,7330 8755,7330 8827.17,7257.83 8827.17,5527.83 8716.34,5417 CN1.3@8716.34,5178.58
UART_TX: A1.1 CN1.2 | length 2417.2
  Bottom Layer w19.68: A1.1@8681.5,7430 8768.22,7430 8898.78,7299.44 8898.78,5493.97 8838.39,5433.58 CN1.2@8838.39,5178.58
VBUS: A1.40 CN1.1 D1.2 D2.2 D3.2 D4.2 D5.2 D6.2 D7.2 D8.2 D9.2 D10.2 D11.2 D12.2 D13.2 D14.2 D15.2 D16.2 D17.2 D18.2 D19.2 D20.2 D21.2 D22.2 D23.2 D24.2 D25.2 D26.2 D27.2 D28.2 D29.2 D30.2 | length 26294.2
  Bottom Layer w19.68: 4208.01,6975 4415,6975 4810,7370 5170,7370 5305,7505 5456.29,7505 5486.29,7535 6355,7535 6410,7480 6970.48,7480 7760,7480 7810,7430 A1.40@7950,7430 8325,7055 8325,5083.03 8406.61,5001.42 CN1.1@8511.61,5001.42
  Bottom Layer w20: D25.2@3650,3695.98 3875.98,3695.98 4010,3830 ; D19.2@3650,4445.98 3959.78,4445.98 3960,4445.76 ; D13.2@3650,5195.98 3958.86,5195.98 3960,5197.12 ; D7.2@3650,5945.98 3958.68,5945.98 3960,5947.31 ; D1.2@3650,6695.98 3959.14,6695.98 3960,6695.13 ; 4208.01,6975 4145,6975 4026.69,6856.69 ; D26.2@4270,3774.72 4269.72,3775 4065,3775 4010,3830 ; D20.2@4270,4524.72 3962.42,4524.72 3960,4527.15 ; D14.2@4270,5274.72 3960.25,5274.72 3960,5274.97 ; D8.2@4270,6024.72 3960.43,6024.72 3960,6025.15 ; D2.2@4270,6774.72 4108.65,6774.72 4026.69,6856.69 ; D27.2@5150,4168.43 5340.07,4168.43 5614.09,4442.45 ; D21.2@5150,4918.43 5454.69,4918.43 5456.29,4920.02 ; D15.2@5150,5668.43 5456.28,5668.43 ; D9.2@5150,6418.43 5455.51,6418.43 5456.29,6419.21 ; D3.2@5150,7168.43 5455.49,7168.43 5456.29,7167.62 ; 5456.29,7505 5456.29,7225 ; D28.2@5770,4286.54 5614.09,4442.45 ; D22.2@5770,5036.54 5457.21,5036.54 5456.29,5037.45 ; D16.2@5770,5786.54 5766.71,5783.25 5456.29,5783.25 ; D10.2@5770,6536.54 5767.68,6534.21 5456.29,6534.21 ; D4.2@5770,7286.54 5616.53,7286.53 5555,7225 5456.29,7225 ; D29.2@6650,3971.57 6981.93,3971.57 7106.28,4095.93 ; D23.2@6650,4721.57 6970.28,4721.57 6970.48,4721.78 ; D17.2@6650,5471.57 6970.1,5471.57 6970.48,5471.96 ; D11.2@6650,6221.57 6969.91,6221.57 6970.48,6222.14 ; D5.2@6650,6971.57 6969.73,6971.57 6970.48,6972.32 ; 6970.48,7480 6970.48,6972.32 ; D30.2@7270,3932.2 7106.28,4095.93 ; D24.2@7270,4682.2 7264.04,4688.16 6970.48,4688.16 ; D18.2@7270,5432.2 7269.17,5433.04 6970.48,5433.04 ; D12.2@7270,6182.2 6973.01,6182.2 6970.48,6179.68 ; D6.2@7270,6932.2 6971.68,6932.2 6970.48,6933.4 ; 3960,4445.76 3960,3880 4010,3830 ; 3960,4445.76 3960,4527.15 ; 3960,4527.15 3960,5197.12 ; 3960,5197.12 3960,5274.97 ; 3960,5274.97 3960,5947.31 ; 3960,5947.31 3960,6025.15 ; 3960,6025.15 3960,6695.13 ; 3960,6695.13 3960,6790 4026.69,6856.69 ; 5456.29,4920.02 5456.29,4600.24 5614.09,4442.45 ; 5456.29,4920.02 5456.29,5037.45 ; 5456.29,5037.45 5456.29,5668.44 ; 5456.29,5668.44 5456.29,5783.25 ; 5456.29,5783.25 5456.29,6419.21 ; 5456.29,6419.21 5456.29,6534.21 ; 5456.29,6534.21 5456.29,7167.62 ; 5456.29,7167.62 5456.29,7225 ; 6970.48,4688.16 6970.48,4231.72 7106.28,4095.93 ; 6970.48,4688.16 6970.48,4721.78 ; 6970.48,4721.78 6970.48,5433.04 ; 6970.48,5433.04 6970.48,5471.96 ; 6970.48,5471.96 6970.48,6179.68 ; 6970.48,6179.68 6970.48,6222.14 ; 6970.48,6222.14 6970.48,6933.4 ; 6970.48,6933.4 6970.48,6972.32
VCC: A1.36 C1.1 C3.1 C5.1 C7.1 C9.1 C11.1 C13.1 C15.1 C17.1 C19.1 C21.1 C23.1 C25.1 C27.1 C29.1 C31.1 C33.1 C35.1 C37.1 C39.1 C41.1 C43.1 C45.1 C47.1 C49.1 C51.1 C53.1 C55.1 C57.1 C59.1 U1.1 U2.1 U3.1 U4.1 U5.1 U6.1 U7.1 U8.1 U9.1 U10.1 U11.1 U12.1 U13.1 U14.1 U15.1 U16.1 U17.1 U18.1 U19.1 U20.1 U21.1 U22.1 U23.1 U24.1 U25.1 U26.1 U27.1 U28.1 U29.1 U30.1 U31.16 U32.16 U33.16 U34.16 | length 38097.9
  Top Layer w20: U25.1@3546.62,3444.09 3546.62,3331.62 v1(3535,3320) 3420,3320 3295,3445 3295,4071.2 ; U19.1@3546.62,4194.09 3546.62,4082.09 v1(3534.53,4070) 3296.2,4070 3295,4071.2 ; U13.1@3546.62,4944.09 3546.62,4832.09 v1(3534.53,4820) 3296.4,4820 3295,4818.6 ; U7.1@3546.62,5694.09 v1(3546.62,5570) 3295.66,5570 3295,5570.66 ; U1.1@3546.62,6444.09 3546.62,6336.62 v1(3535,6325) 3295.33,6325 3295,6325.33 ; v1(4090,5610) 4090,5557.7 U31.16@4092.7,5555 ; v1(4284.53,5645) 4296.62,5657.09 U8.1@4296.62,5772.83 ; U26.1@4296.62,3522.83 4295,3521.22 v1(4295,3370) 4215,3450 4215,3805 4290,3880 4340.11,3880 ; U20.1@4296.62,4272.83 4296.62,4161.62 v1(4285,4150) 4340.11,4094.89 4340.11,3880 ; U14.1@4296.62,5022.83 4295,5021.22 v1(4295,4850) 4295,4805 v1(4380,4720) ; U2.1@4296.62,6522.83 4296.62,6416.62 v1(4285,6405) 4285,6295 4370,6210 4683.63,6210 4685,6211.37 ; v1(4595,4720) 4682.94,4720 4685,4722.06 ; v1(4600,5520) 4684.5,5520 4685,5520.5 ; U27.1@5046.62,3916.54 5046.62,3826.62 v1(5035,3815) 4773.75,3815 4576.87,4011.87 ; U21.1@5046.62,4666.54 5046.62,4561.62 v1(5035,4550) 4685.2,4550 4685,4549.8 ; U15.1@5046.62,5416.54 5046.62,5311.62 v1(5035,5300) 4686.19,5300 4685,5298.81 ; U9.1@5046.62,6166.54 5046.62,6067.09 v1(5034.53,6055) 4685.11,6055 4685,6054.89 ; U3.1@5046.62,6916.54 5046.62,6817.09 v1(5034.53,6805) 4686.25,6805 4685,6806.25 ; U32.16@5577.7,6030 5580,6032.3 v1(5580,6100) ; U33.16@5652.7,3770 5652.7,3793.17 v1(5784.53,3925) 5796.62,3937.09 U28.1@5796.62,4034.65 ; v1(5785,6180) 5796.62,6191.62 U10.1@5796.62,6284.65 ; U22.1@5796.62,4784.65 5796.62,4691.62 v1(5785,4680) 5785,4595 5880,4500 6120.02,4500 ; U16.1@5796.62,5534.65 5796.62,5442.09 v1(5784.53,5430) 5784.53,5385.47 5883.53,5286.47 6120.02,5286.47 ; U4.1@5796.62,7034.65 5796.62,6936.62 v1(5785,6925) 5700,7010 5700,7350 ; v1(6075,6055) 6120.02,6055 ; v1(6080,3802.31) 6117.67,3839.98 6120.02,3839.98 ; U29.1@6546.62,3719.69 6546.62,3626.62 v1(6535,3615) 6345,3615 6120.02,3839.98 ; U23.1@6546.62,4469.69 6546.62,4376.62 v1(6535,4365) 6121.12,4365 6120.02,4366.11 ; U17.1@6546.62,5219.69 6546.62,5126.62 v1(6535,5115) 6121.08,5115 6120.02,5113.93 ; U11.1@6546.62,5969.69 6546.62,5871.62 v1(6535,5860) 6120.7,5860 6120.02,5859.31 ; U5.1@6546.62,6719.69 6546.62,6627.09 v1(6534.53,6615) 6120.97,6615 6120.02,6615.95 ; U34.16@7072.7,5865 v1(7072.7,5905) ; v1(7284.53,6580) 7296.62,6592.09 U6.1@7296.62,6680.31 7116.57,6860.36 7116.57,7305 ; U30.1@7296.62,3680.32 7296.62,3586.62 v1(7285,3575) 7285,3475 7352.5,3407.5 7447.5,3407.5 7590,3550 7590,4156.71 ; U24.1@7296.62,4430.31 7296.62,4332.09 v1(7284.53,4320) 7284.53,4205.47 7335,4155 7588.29,4155 7590,4156.71 ; U18.1@7296.62,5180.31 7296.62,5087.09 v1(7284.53,5075) 7284.53,4980.47 7426.49,4838.51 7590,4838.51 ; U12.1@7296.62,5930.31 7296.62,5836.62 v1(7285,5825) 7285,5765 7400,5650 7589.19,5650 7590,5650.81 ; A1.36@7950,7030 7812.4,7167.6 ; 3295,4071.2 3295,4818.6 ; 3295,4818.6 3295,5570.66 ; 3295,5570.66 3295,6325.33 ; 3295,6325.33 3295,6760 3417.5,6882.5 4462.5,6882.5 4642.41,7062.41 4687.41,7062.41 ; 4340.11,3880 4445,3880 4576.87,4011.87 ; 4576.87,4011.87 4685,4120 4685,4549.8 ; 4685,4549.8 4685,4722.06 ; 4685,4722.06 4685,5298.81 ; 4685,5298.81 4685,5520.5 ; 4685,5520.5 4685,6054.89 ; 4685,6054.89 4685,6211.37 ; 4685,6211.37 4685,6806.25 ; 4685,6806.25 4685,7060 4687.41,7062.41 ; 4687.41,7062.41 4850,7225 5225,7225 5350,7350 5700,7350 ; 5700,7350 6120.02,7350 ; 6120.02,3839.98 6120.02,4366.11 ; 6120.02,4366.11 6120.02,4500 ; 6120.02,4500 6120.02,5113.93 ; 6120.02,5113.93 6120.02,5286.47 ; 6120.02,5286.47 6120.02,5859.31 ; 6120.02,5859.31 6120.02,6055 ; 6120.02,6055 6120.02,6615.95 ; 6120.02,6615.95 6120.02,7350 ; 6120.02,7350 6315.02,7350 6360.02,7305 7116.57,7305 ; 7116.57,7305 7675,7305 7812.4,7167.6 ; 7590,4156.71 7590,4838.51 ; 7590,4838.51 7590,5650.81 ; 7590,5650.81 7590,5875 7715,6000 7715,7070.2 7812.4,7167.6
  Bottom Layer w20: C49.1@3534.53,3394.09 3535,3393.62 v1(3535,3320) ; v1(3534.53,4070) C37.1@3534.53,4144.09 ; v1(3534.53,4820) C25.1@3534.53,4894.09 ; C13.1@3534.53,5644.09 3534.53,5582.09 v1(3546.62,5570) ; C1.1@3534.53,6394.09 3535,6393.62 v1(3535,6325) ; v1(4090,5610) 4125,5645 v1(4284.53,5645) ; C51.1@4284.53,3472.83 4284.53,3380.47 v1(4295,3370) ; C39.1@4284.53,4222.83 4284.53,4150.47 v1(4285,4150) ; C27.1@4284.53,4972.83 4284.53,4860.47 v1(4295,4850) ; C15.1@4284.53,5722.83 v1(4284.53,5645) ; C3.1@4284.53,6472.83 4285,6472.36 v1(4285,6405) ; v1(4380,4720) v1(4595,4720) ; v1(4600,5520) 4355,5520 4284.53,5590.47 v1(4284.53,5645) ; C53.1@5034.53,3866.54 5035,3866.06 v1(5035,3815) ; C41.1@5034.53,4616.54 5035,4616.06 v1(5035,4550) ; C29.1@5034.53,5366.54 5035,5366.06 v1(5035,5300) ; v1(5034.53,6055) C17.1@5034.53,6116.54 ; v1(5034.53,6805) C5.1@5034.53,6866.54 ; v1(5580,6100) 5660,6180 v1(5785,6180) ; C55.1@5784.53,3984.65 v1(5784.53,3925) 5785,3924.53 5785,3850 5832.69,3802.31 v1(6080,3802.31) ; C43.1@5784.53,4734.65 5785,4734.17 v1(5785,4680) ; v1(5784.53,5430) C31.1@5784.53,5484.65 ; C19.1@5784.53,6234.65 5785,6234.17 v1(5785,6180) ; C7.1@5784.53,6984.65 5785,6984.17 v1(5785,6925) ; v1(6075,6055) 5835,6055 5785,6105 v1(5785,6180) ; C57.1@6534.53,3669.69 6535,3669.21 v1(6535,3615) ; C45.1@6534.53,4419.69 6535,4419.21 v1(6535,4365) ; C33.1@6534.53,5169.69 6535,5169.21 v1(6535,5115) ; C21.1@6534.53,5919.69 6535,5919.21 v1(6535,5860) ; v1(6534.53,6615) C9.1@6534.53,6669.69 ; v1(7072.7,5905) 7115,5905 7195,5825 v1(7285,5825) 7284.53,5825.47 C23.1@7284.53,5880.31 ; C59.1@7284.53,3630.32 7285,3629.84 v1(7285,3575) ; v1(7284.53,4320) C47.1@7284.53,4380.31 ; v1(7284.53,5075) C35.1@7284.53,5130.31 ; v1(7284.53,6580) C11.1@7284.53,6630.31
pads on no net: A1. A1.4 A1.5 A1.6 A1.7 A1.9 A1.10 A1.11 A1.12 A1.14 A1.15 A1.16 A1.17 A1.19 A1.20 A1.22 A1.30 A1.33 A1.35 A1.37 A1.39 U31.6 U32.6 U33.4 U33.6 U33.12 U34.6

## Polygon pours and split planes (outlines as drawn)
GND on Top Layer (solid, remove dead copper, pour order 0): 3197.8,7070 4240,7070 4605,7435 5145,7435 5295,7585 6385,7585 6460,7510 8980,7510 8980,4899.78 8827.25,4760 8420,4760 8195,4535 8195,3239.14 7976.32,3000 3190,3000 3000,3215 3025,6900
GND on Bottom Layer (solid, remove dead copper, pour order 2): 3197.8,7070 4240,7070 4605,7435 5145,7435 5295,7585 6385,7585 6460,7510 8980,7510 8980,4899.78 8827.25,4760 8420,4760 8195,4535 8195,3239.14 7976.32,3000 3190,3000 3000,3215 3025,6900

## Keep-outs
Board Outline Layer:
  circle w1: c3706.43,6110.85 r39.37
  region: 3745.8,6110.85 cw(c3706.43,6110.85) 3667.06,6110.85 cw(c3706.43,6110.85)
  circle w1: c7390,7135 r39.37
  region: 7429.37,7135 cw(c7390,7135) 7350.63,7135 cw(c7390,7135)
  circle w1: c5670.51,5192.69 r39.37
  region: 5709.88,5192.69 cw(c5670.51,5192.69) 5631.14,5192.69 cw(c5670.51,5192.69)
  circle w1: c8010,3675 r39.37
  region: 8049.37,3675 cw(c8010,3675) 7970.63,3675 cw(c8010,3675)
  circle w1: c3725,3855 r39.37
  region: 3764.37,3855 cw(c3725,3855) 3685.63,3855 cw(c3725,3855)
  lines w10: 3025,3221.22 3190,3000 ; 3025,3221.22 3025,6900 ; 3025,3221.22 3190,3000 ; 3025,3221.22 3025,6900 ; 3025,6900 3197.8,7070 ; 3025,6900 3197.8,7070 ; 3190,3000 7976.32,3000 ; 3190,3000 7976.32,3000 ; 3197.8,7070 4240,7070 ; 3197.8,7070 4240,7070 ; 4240,7070 4605,7435 ; 4240,7070 4605,7435 ; 4605,7435 5145,7435 ; 4605,7435 5145,7435 ; 5145,7435 5295,7585 ; 5145,7435 5295,7585 ; 5295,7585 6385,7585 ; 5295,7585 6385,7585 ; 6385,7585 6460,7510 ; 6385,7585 6460,7510 ; 6460,7510 8980,7510 ; 6460,7510 8980,7510 ; 7976.32,3000 8195,3239.14 ; 7976.32,3000 8195,3239.14 ; 8195,3239.14 8195,4535 ; 8195,3239.14 8195,4535 ; 8195,4535 8420,4760 ; 8195,4535 8420,4760 ; 8420,4760 8827.25,4760 ; 8420,4760 8827.25,4760 ; 8827.25,4760 8980,4899.78 ; 8827.25,4760 8980,4899.78 ; 8980,4899.78 8980,7510 ; 8980,4899.78 8980,7510

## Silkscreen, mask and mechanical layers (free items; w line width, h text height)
Mechanical Layer:
  circle w1: c3706.43,6110.85 r39.37
  circle w1: c7390,7135 r39.37
  circle w1: c5670.51,5192.69 r39.37
  circle w1: c8010,3675 r39.37
  circle w1: c3725,3855 r39.37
